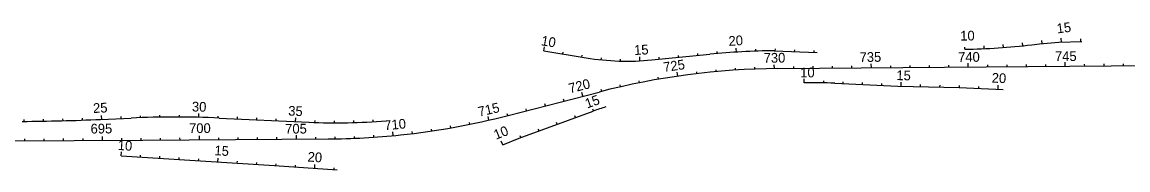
# Model space of a CAD drawing. Extents: x 448091 to 665917, y 1461380 to 1587607.
# Drawn here: x 537266 to 542967, y 1528035 to 1528794 of the extents above; entities that cross this region are included whole.
import ezdxf

# ---------------------------------------------------------------- set-up
doc = ezdxf.new("R2010")
doc.units = 0
doc.layers.add('TextShtNo', color=7, linetype='Continuous')
doc.layers.add('TextTitle', color=7, linetype='Continuous')

msp = doc.modelspace()

# ---------------------------------------------------------------- linework, layer by layer
at = {"layer": 'TextShtNo'}
for p, q in [((542471.3, 1528678.2), (542510.8, 1528683.1)), ((542510.8, 1528683.1), (542611.6, 1528691.5)), ((542611.6, 1528691.5), (542729.1, 1528694.3)), ((539955.5, 1528646.9), (540174.5, 1528610.9)), ((540512.4, 1528599.8), (540812.1, 1528629.2)), ((541143.4, 1528647.6), (541366, 1528637.4)), ((541163.2, 1528555.8), (546176.9, 1528596.1)), ((541456.1, 1528480), (541780.4, 1528465.6)), ((539772.8, 1528314.5), (540240.5, 1528435)), ((541780.4, 1528465.6), (542098.3, 1528458.7)), ((542098.3, 1528458.7), (542324.6, 1528448.2)), ((539829.2, 1528197.4), (540210.7, 1528337.3)), ((537671, 1528294.2), (537828.1, 1528301.3)), ((538282.6, 1528301), (538745.3, 1528279.6)), ((537888.9, 1528187.8), (538843.5, 1528193.7)), ((539744.3, 1528163.6), (539829.2, 1528197.4)), ((537180, 1528183.4), (537888.9, 1528187.8)), ((537776.7, 1528107.1), (538567, 1528056.8)), ((538567, 1528056.8), (538890.8, 1528034.9))]:
    msp.add_line(p, q, dxfattribs=at)
for centre, radius, start, end in [((542102, 1531655.4), 3000, 270.4612, 277.0706), ((540385.6, 1529893.6), 1300, 260.6552, 275.601), ((541193.9, 1524736.2), 3911.7, 90.7399, 95.601), ((541193.9, 1524736.2), 3819.7, 90.4612, 104.4536), ((541323.2, 1525483), 3000, 87.4612, 90.4612), ((538052, 1523306.3), 5000, 87.3567, 92.5668), ((538819.7, 1532013.4), 3819.7, 275.9686, 284.4489), ((540469, 1527633.2), 750, 104.9082, 110.1428), ((537200.8, 1538783.7), 10500, 270.35667, 272.56679), ((538883.7, 1531276.4), 3000, 267.3567, 274.9608), ((538819.7, 1532013.4), 3819.7, 270.3567, 275.9686)]:
    msp.add_arc(centre, radius, start, end, dxfattribs=at)
at = {"layer": 'TextTitle'}
for p, q in [((542624.5, 1528691.8), (542624.1, 1528711.8)), ((542724.5, 1528694.2), (542724.2, 1528709.2)), ((539955.5, 1528646.9), (539958.7, 1528666.6)), ((540949.5, 1528640.2), (540948.2, 1528660.2)), ((541049.4, 1528645.2), (541049, 1528655.2)), ((541149.3, 1528647.3), (541149.8, 1528657.3)), ((541249.2, 1528642.7), (541249.7, 1528652.7)), ((542126.1, 1528655.5), (542126.1, 1528665.5)), ((542226.1, 1528658), (542225.5, 1528673)), ((542325.9, 1528663.8), (542324.8, 1528678.8)), ((542425.5, 1528672.9), (542423.9, 1528687.8)), ((542524.8, 1528684.3), (542523.6, 1528699.3)), ((540054.1, 1528630.7), (540055.8, 1528640.5)), ((540152.8, 1528614.4), (540154.4, 1528624.3)), ((540251.8, 1528600.5), (540252.8, 1528610.5)), ((540351.6, 1528594.1), (540351.8, 1528604.1)), ((540451.6, 1528595.3), (540450.5, 1528615.3)), ((540551.2, 1528603.6), (540550.2, 1528613.6)), ((540650.7, 1528613.4), (540649.7, 1528623.3)), ((540750.2, 1528623.1), (540749.3, 1528633.1)), ((540849.8, 1528632.7), (540848.9, 1528642.7)), ((541349.1, 1528638.2), (541349.6, 1528648.2)), ((540646.5, 1528516.5), (540643.6, 1528536.3)), ((540745.6, 1528529.5), (540744.5, 1528539.4)), ((540845.1, 1528539.9), (540844.2, 1528549.9)), ((540944.8, 1528547.8), (540944.1, 1528557.7)), ((541044.6, 1528553), (541044.3, 1528563)), ((541144.6, 1528555.6), (541144.3, 1528575.6)), ((541244.6, 1528556.4), (541244.5, 1528566.4)), ((541344.6, 1528557.2), (541344.5, 1528567.2)), ((541444.6, 1528558), (541444.5, 1528568)), ((541544.6, 1528558.8), (541544.5, 1528568.8)), ((541644.6, 1528559.6), (541644.4, 1528579.6)), ((541744.6, 1528560.4), (541744.5, 1528570.4)), ((541844.6, 1528561.3), (541844.5, 1528571.3)), ((541944.6, 1528562.1), (541944.5, 1528572.1)), ((542044.6, 1528562.9), (542044.5, 1528572.9)), ((542144.6, 1528563.7), (542144.4, 1528583.7)), ((542244.6, 1528564.5), (542244.5, 1528574.5)), ((542344.6, 1528565.3), (542344.5, 1528575.3)), ((542444.6, 1528566.1), (542444.5, 1528576.1)), ((542544.6, 1528566.9), (542544.5, 1528576.9)), ((542644.6, 1528567.7), (542644.4, 1528587.7)), ((542744.6, 1528568.5), (542744.5, 1528578.5)), ((542844.5, 1528569.3), (542844.5, 1528579.3)), ((542944.5, 1528570.1), (542944.5, 1528580.1)), ((540449.4, 1528482.6), (540447.5, 1528492.4)), ((540547.7, 1528500.8), (540546, 1528510.7)), ((541299, 1528482.9), (541298.9, 1528502.9)), ((541399, 1528482), (541399.3, 1528492)), ((541498.9, 1528478.1), (541499.4, 1528488.1)), ((541598.8, 1528473.7), (541599.3, 1528483.7)), ((541698.7, 1528469.3), (541699.2, 1528479.2)), ((541798.7, 1528465.2), (541799.1, 1528485.2)), ((540157.5, 1528413.6), (540152.5, 1528433)), ((540254.3, 1528438.5), (540251.9, 1528448.2)), ((540351.6, 1528461.9), (540349.4, 1528471.6)), ((541898.6, 1528463), (541898.9, 1528473)), ((541998.6, 1528460.8), (541998.8, 1528470.8)), ((542098.6, 1528458.6), (542099.1, 1528468.6)), ((542198.5, 1528454), (542198.9, 1528464)), ((542298.4, 1528449.4), (542299.3, 1528469.4)), ((539963.8, 1528363.7), (539961.3, 1528373.4)), ((540060.7, 1528388.6), (540058.2, 1528398.3)), ((537676.9, 1528294.5), (537676, 1528314.5)), ((537776.8, 1528299), (537776.4, 1528309)), ((537876.7, 1528303.2), (537876.4, 1528313.2)), ((537976.7, 1528305.7), (537976.6, 1528315.7)), ((538076.7, 1528306.2), (538076.8, 1528316.2)), ((538176.7, 1528304.7), (538177.2, 1528324.7)), ((538276.6, 1528301.3), (538277.1, 1528311.2)), ((538376.5, 1528296.6), (538377, 1528306.6)), ((539673, 1528290.2), (539668.5, 1528309.7)), ((539770.2, 1528313.8), (539767.7, 1528323.5)), ((539867, 1528338.7), (539864.5, 1528348.4)), ((540119, 1528303.6), (540115.5, 1528313)), ((540212.8, 1528338.1), (540209.4, 1528347.5)), ((537277.1, 1528284), (537277, 1528294)), ((537377.1, 1528285.2), (537376.9, 1528295.2)), ((537477.1, 1528287.3), (537476.8, 1528297.3)), ((537577, 1528290.5), (537576.7, 1528300.4)), ((538476.4, 1528292), (538476.9, 1528302)), ((538576.3, 1528287.4), (538576.8, 1528297.4)), ((538676.2, 1528282.8), (538677.1, 1528302.8)), ((538776.1, 1528278.4), (538776.5, 1528288.4)), ((538876.1, 1528276.4), (538876.1, 1528286.4)), ((538976.1, 1528277.9), (538975.8, 1528287.8)), ((539075.9, 1528282.6), (539075.3, 1528292.6)), ((539477, 1528250.6), (539475.2, 1528260.5)), ((539575.2, 1528269.1), (539573.3, 1528278.9)), ((540025.1, 1528269.2), (540021.6, 1528278.6)), ((537280.3, 1528184), (537280.2, 1528194)), ((537380.3, 1528184.6), (537380.2, 1528194.6)), ((537480.3, 1528185.2), (537480.2, 1528195.2)), ((537580.3, 1528185.9), (537580.2, 1528195.9)), ((537680.3, 1528186.5), (537680.1, 1528206.5)), ((537780.3, 1528187.1), (537780.2, 1528197.1)), ((537880.3, 1528187.7), (537880.2, 1528197.7)), ((537980.3, 1528188.4), (537980.2, 1528198.4)), ((538080.3, 1528189), (538080.2, 1528199)), ((538180.3, 1528189.6), (538180.1, 1528209.6)), ((538280.3, 1528190.2), (538280.2, 1528200.2)), ((538380.3, 1528190.8), (538380.2, 1528200.8)), ((538480.3, 1528191.5), (538480.2, 1528201.5)), ((538580.3, 1528192.1), (538580.2, 1528202.1)), ((538680.2, 1528192.7), (538680.1, 1528212.7)), ((538780.2, 1528193.3), (538780.2, 1528203.3)), ((538880.2, 1528194.1), (538880.1, 1528204.1)), ((538980.2, 1528197), (538979.8, 1528207)), ((539080, 1528202.5), (539079.4, 1528212.5)), ((539179.7, 1528210.7), (539177.8, 1528230.6)), ((539279.1, 1528221.4), (539277.9, 1528231.3)), ((539378.2, 1528234.7), (539376.8, 1528244.6)), ((539837.3, 1528200.3), (539833.9, 1528209.7)), ((539931.2, 1528234.8), (539927.7, 1528244.2)), ((539744.3, 1528163.6), (539736.9, 1528182.2)), ((537776.7, 1528107.1), (537778, 1528127)), ((537876.5, 1528100.7), (537877.1, 1528110.7)), ((537976.3, 1528094.4), (537976.9, 1528104.4)), ((538076.1, 1528088), (538076.7, 1528098)), ((538175.9, 1528081.7), (538176.5, 1528091.7)), ((538275.7, 1528075.3), (538277, 1528095.3)), ((538375.5, 1528069), (538376.1, 1528078.9)), ((538475.3, 1528062.6), (538475.9, 1528072.6)), ((538575.1, 1528056.2), (538575.8, 1528066.2)), ((538674.9, 1528049.5), (538675.5, 1528059.4)), ((538774.6, 1528042.7), (538776, 1528062.7)), ((538874.4, 1528036), (538875.1, 1528045.9))]:
    msp.add_line(p, q, dxfattribs=at)

# ---------------------------------------------------------------- texts
for s, rotation, p in [('15', 7.0706, (542603.3, 1528736)), ('10', 350.6551, (539939.8, 1528675.9)), ('20', 3.5827, (540910, 1528672)), ('10', 0.4612, (542103.1, 1528699.6)), ('15', 2.9103, (540422.9, 1528625.2)), ('725', 8.2399, (540575.7, 1528537.3)), ('730', 0.7399, (541089.8, 1528585.2)), ('735', 0.4612, (541584.3, 1528589.6)), ('740', 0.4612, (542092.3, 1528589.7)), ('745', 0.4612, (542591.7, 1528593.7)), ('10', 0.4612, (541278.1, 1528510.1)), ('15', 358.7443, (541773.4, 1528496.3)), ('720', 14.4489, (540091, 1528428)), ('20', 357.3594, (542264.4, 1528483.6)), ('25', 2.5668, (537633, 1528327)), ('30', 358.5712, (538141.2, 1528335.2)), ('35', 357.3567, (538637.3, 1528314.1)), ('715', 12.9081, (539622.8, 1528307.9)), ('15', 19.9727, (540179.3, 1528349.7)), ('695', 0.3567, (537619.4, 1528221.5)), ('700', 0.3567, (538127.2, 1528223.6)), ('705', 0.3567, (538622.7, 1528220.9)), ('710', 5.4081, (539136.1, 1528237.7)), ('10', 21.6946, (539709.5, 1528189.2)), ('10', 356.3567, (537758.2, 1528137.3)), ('15', 356.3567, (538256.6, 1528110.4)), ('20', 356.1283, (538736.9, 1528077.8))]:
    msp.add_text(s, height=50, rotation=rotation, dxfattribs=at).set_placement(p)

doc.saveas('drawing.dxf')
